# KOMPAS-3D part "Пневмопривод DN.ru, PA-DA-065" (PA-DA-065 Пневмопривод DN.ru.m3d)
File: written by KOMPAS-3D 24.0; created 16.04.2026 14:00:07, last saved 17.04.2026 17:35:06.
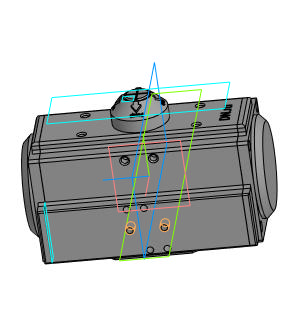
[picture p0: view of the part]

Document properties: Автор: DN.ru; Полное имя файла: C:\Работа\PA-DA-х Пневмопривод DN.ru\065\исходные материалы\PA-DA-065 Пневмопривод DN.ru.m3d

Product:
- Body: Тело 1  | qty 1
    Масса: 8.171048
- Body: Тело 2  | qty 1
    Масса: 8.171048
- Part/product: Пневмопривод DN.ru  | designation PA-DA-065
    Масса: 2
    Раздел спецификации: Прочие изделия
    Примечание: D290-00294

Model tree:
1. Эскиз:1
2. Элемент выдавливания:1
3. Эскиз:2  (with: Ребро.Элемент выдавливания:1)
4. Элемент выдавливания:2
5. Эскиз:3  (with: Ребро.Элемент выдавливания:2)
6. Элемент выдавливания:3  (with: Грань.Элемент выдавливания:2)
     Смещение 1 = -2; Расстояние 2 = 74.5; Смещение 2 = -2
7. Эскиз:4  (with: Грань.Элемент выдавливания:3, Ребро.Элемент выдавливания:3)
8. Элемент выдавливания:4
9. Эскиз:6  (with: Ребро.Элемент выдавливания:2)
10. Элемент выдавливания:6
11. Отверстие:2  (with: Грань.Элемент выдавливания:6)
     Глубина выреза = 10; Диаметр отверстия = 5; Угол конуса дна = 120; Расстояние 2 = 4
12. Массив по сетке:2  (with: Отверстие:2)  (3 pattern instances)
     Шаг 1 = 12; Угол раствора = 90; Шаг 2 = 32
13. Массив по сетке:3  (with: Отверстие:2)  (2 pattern instances)
     Шаг 1 = 32; Угол раствора = 90; Шаг 2 = 12
14. Отверстие:3  (with: Грань.Элемент выдавливания:6, Ребро.Элемент выдавливания:6)  (labels: W 1/4'')
     Глубина выреза = 10; Диаметр отверстия = 4.72357; Угол конуса дна = 120; Расстояние 1 = 12; Расстояние 2 = 20
15. W 1/4''  (with: Грань.Отверстие:3, Грань.Элемент выдавливания:6)  (labels: cil5_ex_DIN 477 BSW coarse)
     Длина резьбы = 8; Шаг резьбы = 1.27; Номинальный диаметр резьбы = 6.35
16. Массив по сетке:4  (with: Отверстие:3)  (labels: W 1/4'')  (2 pattern instances)
17. Эскиз:7  (with: Грань.Элемент выдавливания:2)
18. Элемент выдавливания:7
19. Эскиз:8  (with: Грань.Элемент выдавливания:2, Ребро.Элемент выдавливания:2)
20. Элемент выдавливания:8  (with: Грань.Элемент выдавливания:6)
     Расстояние 2 = 4
21. Отверстие:4  (with: Грань.Элемент выдавливания:2)
     Глубина выреза = 7; Диаметр отверстия = 5; Угол конуса дна = 118; Расстояние 1 = 6; Расстояние 2 = 10; Диаметр зенковки = 7; Глубина зенковки = 1; Угол зенковки = 90
22. Массив по сетке:5  (with: Отверстие:4)  (2 pattern instances)
     Шаг 1 = 20; Угол раствора = 90
23. Отверстие:5  (with: Грань.Элемент выдавливания:3)
     Глубина выреза = 10; Диаметр отверстия = 5; Угол конуса дна = 120; Диаметр зенковки = 7; Глубина зенковки = 1; Угол зенковки = 90
24. Массив по сетке:6  (with: Отверстие:5)  (4 pattern instances)
     Угол раствора = 90
25. Фаска:1  (with: Ребро.Элемент выдавливания:4)
     Угол = 45; Длина 1 = 10; Длина 2 = 10
26. Скругление:2  (with: Ребро.Элемент выдавливания:3)
     Радиус = 2
27. Скругление:3  (with: Ребро.Элемент выдавливания:6)
     Радиус = 2
28. Скругление:4  (with: Ребро.Элемент выдавливания:8, Ребро.Элемент выдавливания:2)
     Радиус = 2
29. Скругление:5  (with: Ребро.Элемент выдавливания:6)
     Радиус = 1
30. Смещенная плоскость:1  (with: Грань.Элемент выдавливания:3)
31. Эскиз:9
32. Элемент выдавливания:9  (with: Грань.Фаска:1)
     Расстояние 1 = 17.4142; Смещение 1 = 1
33. Смещенная плоскость:2  (with: Грань.Элемент выдавливания:4)
     Расстояние = 0.5
34. Эскиз:10
35. Элемент выдавливания:10
     Расстояние 1 = 10.9142
36. Эскиз:11  (with: Грань.Элемент выдавливания:4)
37. Элемент выдавливания:11
     Расстояние 1 = 1
38. Эскиз:12  (with: Грань.Элемент выдавливания:11)
39. Элемент выдавливания:12  (with: Грань.Элемент выдавливания:4)
     Расстояние 2 = 1
40. Эскиз:13  (with: Грань.Элемент выдавливания:11)
41. Элемент выдавливания:13  (with: Грань.Элемент выдавливания:4)
     Расстояние 2 = 1
42. Скругление:7  (with: Ребро.Элемент выдавливания:11)
     Радиус = 1
43. Скругление:8  (with: Ребро.Элемент выдавливания:8, Ребро.Элемент выдавливания:2)
     Радиус = 2
44. Эскиз:14  (with: Грань.Элемент выдавливания:3)
45. Элемент выдавливания:14  (with: Грань.Фаска:1)
     Расстояние 1 = 29.1414; Смещение 1 = 0.1
46. Эскиз:15  (with: Грань.Элемент выдавливания:3, Ребро.Скругление:2)
47. Элемент выдавливания:15
     Расстояние 2 = 0.1
48. Отверстие:6  (with: Грань.Элемент выдавливания:2, Ребро.Элемент выдавливания:2)
     Глубина выреза = 10; Диаметр отверстия = 8; Угол конуса дна = 118; Расстояние 1 = 5; Расстояние 2 = 5
49. Зеркальный массив:1
50. Экземпляр ( 1 )
51. Экземпляр ( 2 )  (with: Отверстие:6)
52. Зеркальный массив:2  (with: Экземпляр ( 1 ), Экземпляр ( 2 ), Отверстие:6)
53. Зеркальный массив:3  (with: Экземпляр ( 1 ), Экземпляр ( 2 ), Зеркальный массив:2, Отверстие:6)
54. Зеркальный массив:4  (with: Экземпляр ( 1 ), Экземпляр ( 2 ), Зеркальный массив:1, Отверстие:6, Зеркальный массив:3, Зеркальный массив:2)
55. Фаска:2  (with: Ребро.Элемент выдавливания:7)
     Угол = 45; Длина 1 = 1; Длина 2 = 1
56. Фаска:3  (with: Ребро.Элемент выдавливания:7)
     Угол = 45; Длина 1 = 1.6; Длина 2 = 1.6
57. Фаска:4  (with: Ребро.Элемент выдавливания:1)
     Угол = 45; Длина 1 = 5; Длина 2 = 5
58. Смещенная плоскость:3  (with: Грань.Элемент выдавливания:6)
     Расстояние = 5
59. Эскиз:16
60. Элемент выдавливания:16
     Расстояние 2 = 0.1
61. Зеркальный массив:5  (with: Экземпляр ( 1 ), Экземпляр ( 2 ), Элемент выдавливания:16)

Expressions: H/2; -G/2; (E-C-1)/2
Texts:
  PA-DA-065
  GOST 26.020 Pr3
